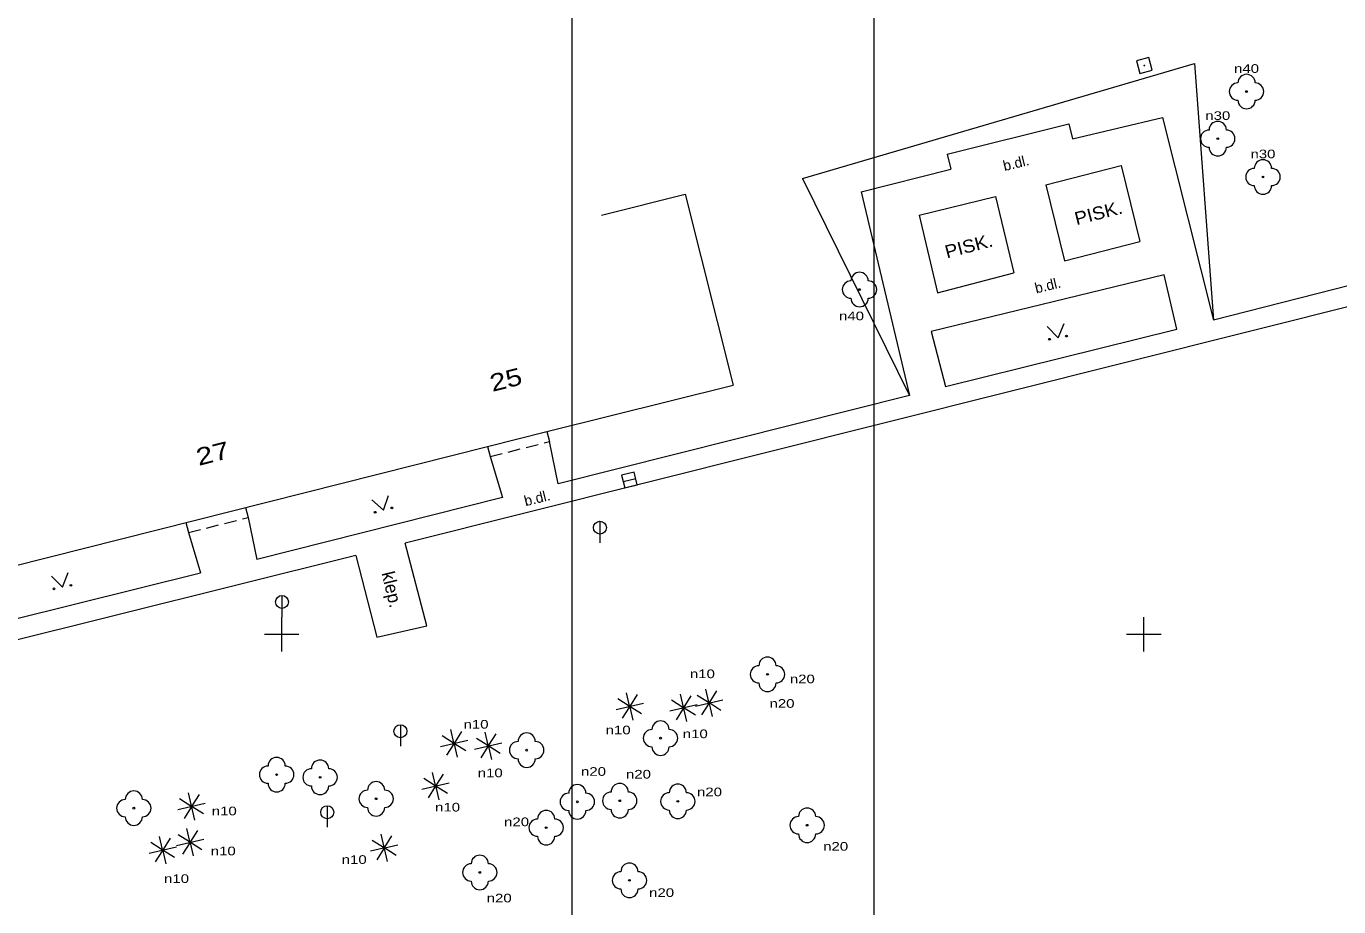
# Model space of a CAD drawing. Extents: x -670514 to -669423, y -1130798 to -1130123.
# Drawn here: x -669864.8 to -669788.7, y -1130615.8 to -1130564.8 of the extents above; entities that cross this region are included whole.
import ezdxf
from ezdxf.enums import TextEntityAlignment as Align

# ---------------------------------------------------------------- set-up
doc = ezdxf.new("R2010")
doc.units = 0
doc.header["$LTSCALE"] = 0.24
doc.linetypes.add('MEDIUM_DASHED', pattern=[4.5, 3, -1.5])
for name, color, linetype, lineweight in [('10', 7, 'Continuous', 13), ('14', 7, 'Continuous', 13), ('22', 7, 'Continuous', 13), ('26', 7, 'Continuous', 13), ('27', 7, 'Continuous', 13), ('36', 7, 'Continuous', 13), ('5', 7, 'Continuous', 13), ('60', 7, 'Continuous', 13), ('61', 7, 'Continuous', 13)]:
    doc.layers.add(name, color=color, linetype=linetype, lineweight=lineweight)
for name, color, linetype in [('40', 7, 'Continuous'), ('42', 7, 'Continuous'), ('44', 7, 'Continuous'), ('47', 7, 'Continuous')]:
    doc.layers.add(name, color=color, linetype=linetype)

msp = doc.modelspace()

# ---------------------------------------------------------------- linework, layer by layer
at = {"layer": '10'}
for p, q in [((-669811.412, -1130572.173), (-669804.351, -1130570.413)), ((-669804.351, -1130570.413), (-669804.142, -1130571.288)), ((-669811.412, -1130572.173), (-669811.191, -1130573.045)), ((-669816.404, -1130574.366), (-669811.191, -1130573.045)), ((-669813.027, -1130575.716), (-669808.608, -1130574.626)), ((-669808.608, -1130574.626), (-669807.545, -1130579.051)), ((-669813.027, -1130575.716), (-669811.961, -1130580.213)), ((-669778.633, -1130577.366), (-669795.958, -1130581.787)), ((-669811.961, -1130580.213), (-669807.545, -1130579.051)), ((-669786.393, -1130580.581), (-669842.834, -1130594.715)), ((-669851.942, -1130593.234), (-669851.442, -1130595.658)), ((-669855.411, -1130594.103), (-669854.71, -1130596.441)), ((-669845.694, -1130595.44), (-669878.012, -1130603.465)), ((-669845.694, -1130595.44), (-669844.483, -1130600.168))]:
    msp.add_line(p, q, dxfattribs=at)
for points in [[(-669804.142, -1130571.288), (-669798.922, -1130570.042), (-669795.958, -1130581.787)], [(-669805.696, -1130573.949), (-669801.327, -1130572.833), (-669800.231, -1130577.238)], [(-669816.404, -1130574.366), (-669813.599, -1130586.153), (-669833.962, -1130591.276), (-669834.473, -1130588.83)], [(-669805.696, -1130573.949), (-669804.6, -1130578.354), (-669800.231, -1130577.238)], [(-669837.918, -1130589.702), (-669837.194, -1130592.065), (-669851.442, -1130595.658)], [(-669844.483, -1130600.168), (-669841.58, -1130599.506), (-669842.834, -1130594.715)], [(-669869.812, -1130597.726), (-669869.347, -1130600.077), (-669854.71, -1130596.441)]]:
    msp.add_lwpolyline(points, dxfattribs=at)
msp.add_lwpolyline([(-669798.093, -1130582.322), (-669798.83, -1130579.158), (-669812.334, -1130582.46), (-669811.499, -1130585.643)], close=True, dxfattribs=at)
at = {"layer": '14'}
msp.add_line((-669819.795, -1130573.588), (-669813.599, -1130586.153), dxfattribs=at)
msp.add_lwpolyline([(-669819.795, -1130573.588), (-669797.073, -1130566.915), (-669795.958, -1130581.787)], dxfattribs=at)
at = {"layer": '22'}
for p, q in [((-669829.827, -1130604.139), (-669829.999, -1130603.385)), ((-669825.223, -1130603.937), (-669825.395, -1130603.183)), ((-669824.781, -1130603.287), (-669825.195, -1130603.943)), ((-669830.613, -1130604.359), (-669829.859, -1130604.187)), ((-669829.853, -1130604.159), (-669830.509, -1130603.745)), ((-669829.839, -1130604.213), (-669830.253, -1130604.869)), ((-669829.385, -1130603.489), (-669829.799, -1130604.145)), ((-669829.129, -1130604.613), (-669829.785, -1130604.199)), ((-669829.779, -1130604.171), (-669829.025, -1130603.999)), ((-669826.733, -1130604.239), (-669827.389, -1130603.825)), ((-669826.707, -1130604.219), (-669826.879, -1130603.465)), ((-669826.265, -1130603.569), (-669826.679, -1130604.225)), ((-669826.659, -1130604.251), (-669825.905, -1130604.079)), ((-669826.009, -1130604.157), (-669825.255, -1130603.985)), ((-669825.249, -1130603.957), (-669825.905, -1130603.543)), ((-669825.235, -1130604.011), (-669825.649, -1130604.667)), ((-669825.207, -1130604.017), (-669825.035, -1130604.771)), ((-669824.525, -1130604.411), (-669825.181, -1130603.997)), ((-669825.175, -1130603.969), (-669824.421, -1130603.797)), ((-669829.811, -1130604.219), (-669829.639, -1130604.973)), ((-669827.493, -1130604.439), (-669826.739, -1130604.267)), ((-669826.719, -1130604.293), (-669827.133, -1130604.949)), ((-669826.691, -1130604.299), (-669826.519, -1130605.053)), ((-669826.009, -1130604.693), (-669826.665, -1130604.279)), ((-669840.013, -1130606.282), (-669840.185, -1130605.528)), ((-669839.571, -1130605.632), (-669839.985, -1130606.288)), ((-669838.029, -1130606.429), (-669838.201, -1130605.675)), ((-669840.799, -1130606.502), (-669840.045, -1130606.33)), ((-669840.039, -1130606.302), (-669840.695, -1130605.888)), ((-669840.025, -1130606.356), (-669840.439, -1130607.012)), ((-669839.997, -1130606.362), (-669839.825, -1130607.116)), ((-669839.315, -1130606.756), (-669839.971, -1130606.342)), ((-669839.965, -1130606.314), (-669839.211, -1130606.142)), ((-669838.815, -1130606.649), (-669838.061, -1130606.477)), ((-669838.055, -1130606.449), (-669838.711, -1130606.035)), ((-669837.587, -1130605.779), (-669838.001, -1130606.435)), ((-669837.331, -1130606.903), (-669837.987, -1130606.489)), ((-669837.981, -1130606.461), (-669837.227, -1130606.289)), ((-669838.041, -1130606.503), (-669838.455, -1130607.159)), ((-669838.013, -1130606.509), (-669837.841, -1130607.263)), ((-669841.081, -1130608.758), (-669841.253, -1130608.004)), ((-669841.107, -1130608.778), (-669841.763, -1130608.364)), ((-669840.639, -1130608.108), (-669841.053, -1130608.764)), ((-669841.033, -1130608.79), (-669840.279, -1130608.618)), ((-669855.263, -1130609.958), (-669855.919, -1130609.544)), ((-669855.237, -1130609.938), (-669855.409, -1130609.184)), ((-669854.795, -1130609.288), (-669855.209, -1130609.944)), ((-669841.867, -1130608.978), (-669841.113, -1130608.806)), ((-669841.093, -1130608.832), (-669841.507, -1130609.488)), ((-669841.065, -1130608.838), (-669840.893, -1130609.592)), ((-669840.383, -1130609.232), (-669841.039, -1130608.818)), ((-669856.023, -1130610.158), (-669855.269, -1130609.986)), ((-669855.249, -1130610.012), (-669855.663, -1130610.668)), ((-669855.221, -1130610.018), (-669855.049, -1130610.772)), ((-669854.539, -1130610.412), (-669855.195, -1130609.998)), ((-669855.189, -1130609.97), (-669854.435, -1130609.798)), ((-669856.908, -1130612.467), (-669857.08, -1130611.713)), ((-669856.466, -1130611.817), (-669856.88, -1130612.473)), ((-669855.349, -1130612.033), (-669856.005, -1130611.619)), ((-669855.323, -1130612.013), (-669855.495, -1130611.259)), ((-669854.881, -1130611.363), (-669855.295, -1130612.019)), ((-669844.066, -1130612.338), (-669844.238, -1130611.584)), ((-669843.624, -1130611.688), (-669844.038, -1130612.344)), ((-669857.694, -1130612.687), (-669856.94, -1130612.515)), ((-669856.934, -1130612.487), (-669857.59, -1130612.073)), ((-669856.92, -1130612.541), (-669857.334, -1130613.197)), ((-669856.892, -1130612.547), (-669856.72, -1130613.301)), ((-669856.21, -1130612.941), (-669856.866, -1130612.527)), ((-669856.86, -1130612.499), (-669856.106, -1130612.327)), ((-669856.109, -1130612.233), (-669855.355, -1130612.061)), ((-669855.335, -1130612.087), (-669855.749, -1130612.743)), ((-669855.307, -1130612.093), (-669855.135, -1130612.847)), ((-669854.625, -1130612.487), (-669855.281, -1130612.073)), ((-669855.275, -1130612.045), (-669854.521, -1130611.873)), ((-669844.852, -1130612.558), (-669844.098, -1130612.386)), ((-669844.092, -1130612.358), (-669844.748, -1130611.944)), ((-669844.078, -1130612.412), (-669844.492, -1130613.068)), ((-669844.05, -1130612.418), (-669843.878, -1130613.172)), ((-669843.368, -1130612.812), (-669844.024, -1130612.398)), ((-669844.018, -1130612.37), (-669843.264, -1130612.198))]:
    msp.add_line(p, q, dxfattribs=at)
for centre, radius in [((-669794.047, -1130568.546), 0.05), ((-669795.717, -1130571.274), 0.05), ((-669793.096, -1130573.496), 0.05), ((-669816.489, -1130580.02), 0.05), ((-669821.829, -1130602.323), 0.05), ((-669829.819, -1130604.179), 0.04), ((-669825.215, -1130603.977), 0.04), ((-669826.699, -1130604.259), 0.04), ((-669840.005, -1130606.322), 0.04), ((-669838.021, -1130606.469), 0.04), ((-669828.03, -1130606.02), 0.05), ((-669835.792, -1130606.715), 0.05), ((-669850.293, -1130608.135), 0.05), ((-669847.773, -1130608.292), 0.05), ((-669841.073, -1130608.798), 0.04), ((-669844.524, -1130609.535), 0.05), ((-669858.575, -1130610.078), 0.05), ((-669855.229, -1130609.978), 0.04), ((-669832.857, -1130609.711), 0.05), ((-669830.396, -1130609.647), 0.05), ((-669827.028, -1130609.685), 0.05), ((-669819.529, -1130611.069), 0.05), ((-669834.662, -1130611.207), 0.05), ((-669856.9, -1130612.507), 0.04), ((-669855.315, -1130612.053), 0.04), ((-669844.058, -1130612.378), 0.04), ((-669838.512, -1130613.803), 0.05), ((-669829.832, -1130614.263), 0.05)]:
    msp.add_circle(centre, radius, dxfattribs=at)
for centre, start, end in [((-669794.047, -1130568.046), 0, 180), ((-669794.547, -1130568.546), 90, 270), ((-669793.547, -1130568.546), 270, 90), ((-669794.047, -1130569.046), 180, 0), ((-669795.717, -1130570.774), 0, 180), ((-669796.217, -1130571.274), 90, 270), ((-669795.217, -1130571.274), 270, 90), ((-669795.717, -1130571.774), 180, 0), ((-669793.596, -1130573.496), 90, 270), ((-669793.096, -1130572.996), 0, 180), ((-669792.596, -1130573.496), 270, 90), ((-669793.096, -1130573.996), 180, 0), ((-669816.489, -1130579.52), 0, 180), ((-669816.989, -1130580.02), 90, 270), ((-669815.989, -1130580.02), 270, 90), ((-669816.489, -1130580.52), 180, 0), ((-669822.329, -1130602.323), 90, 270), ((-669821.829, -1130601.823), 0, 180), ((-669821.329, -1130602.323), 270, 90), ((-669821.829, -1130602.823), 180, 0), ((-669835.792, -1130606.215), 0, 180), ((-669828.53, -1130606.02), 90, 270), ((-669828.03, -1130605.52), 0, 180), ((-669827.53, -1130606.02), 270, 90), ((-669836.292, -1130606.715), 90, 270), ((-669835.292, -1130606.715), 270, 90), ((-669850.293, -1130607.635), 0, 180), ((-669835.792, -1130607.215), 180, 0), ((-669828.03, -1130606.52), 180, 0), ((-669850.793, -1130608.135), 90, 270), ((-669849.793, -1130608.135), 270, 90), ((-669848.273, -1130608.292), 90, 270), ((-669847.773, -1130607.792), 0, 180), ((-669847.273, -1130608.292), 270, 90), ((-669850.293, -1130608.635), 180, 0), ((-669844.524, -1130609.035), 0, 180), ((-669832.857, -1130609.211), 0, 180), ((-669830.396, -1130609.147), 0, 180), ((-669827.028, -1130609.185), 0, 180), ((-669858.575, -1130609.578), 0, 180), ((-669847.773, -1130608.792), 180, 0), ((-669845.024, -1130609.535), 90, 270), ((-669844.024, -1130609.535), 270, 90), ((-669833.357, -1130609.711), 90, 270), ((-669832.357, -1130609.711), 270, 90), ((-669830.896, -1130609.647), 90, 270), ((-669829.896, -1130609.647), 270, 90), ((-669827.528, -1130609.685), 90, 270), ((-669826.528, -1130609.685), 270, 90), ((-669859.075, -1130610.078), 90, 270), ((-669858.075, -1130610.078), 270, 90), ((-669844.524, -1130610.035), 180, 0), ((-669834.662, -1130610.707), 0, 180), ((-669832.857, -1130610.211), 180, 0), ((-669830.396, -1130610.147), 180, 0), ((-669827.028, -1130610.185), 180, 0), ((-669819.529, -1130610.569), 0, 180), ((-669858.575, -1130610.578), 180, 0), ((-669835.162, -1130611.207), 90, 270), ((-669834.162, -1130611.207), 270, 90), ((-669820.029, -1130611.069), 90, 270), ((-669819.029, -1130611.069), 270, 90), ((-669834.662, -1130611.707), 180, 0), ((-669819.529, -1130611.569), 180, 0), ((-669839.012, -1130613.803), 90, 270), ((-669838.512, -1130613.303), 0, 180), ((-669838.012, -1130613.803), 270, 90), ((-669829.832, -1130613.763), 0, 180), ((-669830.332, -1130614.263), 90, 270), ((-669829.332, -1130614.263), 270, 90), ((-669838.512, -1130614.303), 180, 0), ((-669829.832, -1130614.763), 180, 0)]:
    msp.add_arc(centre, 0.5, start, end, dxfattribs=at)
at = {"layer": '26'}
msp.add_lwpolyline([(-669800.241, -1130567.49), (-669799.516, -1130567.299), (-669799.707, -1130566.574), (-669800.432, -1130566.765)], close=True, dxfattribs=at)
msp.add_circle((-669799.9739, -1130567.032), 0.02, dxfattribs=at)
at = {"layer": '27'}
for p, q in [((-669830.195, -1130591.152), (-669829.467, -1130590.972)), ((-669831.546, -1130593.445), (-669831.546, -1130594.695)), ((-669849.984, -1130597.75), (-669849.984, -1130599)), ((-669843.115, -1130605.244), (-669843.115, -1130606.494)), ((-669847.36, -1130609.939), (-669847.36, -1130611.189))]:
    msp.add_line(p, q, dxfattribs=at)
msp.add_lwpolyline([(-669830.105, -1130591.515), (-669829.377, -1130591.335), (-669829.557, -1130590.607), (-669830.285, -1130590.787)], close=True, dxfattribs=at)
for centre in [(-669831.5456, -1130593.8201), (-669849.9836, -1130598.1251), (-669843.1146, -1130605.6191), (-669847.3596, -1130610.3141)]:
    msp.add_circle(centre, 0.375, dxfattribs=at)
at = {"layer": '36'}
for points in [[(-669805.611, -1130582.164), (-669804.981, -1130582.81), (-669804.628, -1130581.98)], [(-669844.768, -1130592.2), (-669844.095, -1130592.8), (-669843.8, -1130591.948)], [(-669863.358, -1130596.632), (-669862.714, -1130597.263), (-669862.379, -1130596.426)]]:
    msp.add_lwpolyline(points, dxfattribs=at)
for centre in [(-669805.4728, -1130582.9015), (-669804.4898, -1130582.7177), (-669843.6111, -1130592.6734), (-669844.5788, -1130592.9257), (-669863.2035, -1130597.3657), (-669862.2249, -1130597.1599)]:
    msp.add_circle(centre, 0.05, dxfattribs=at)
at = {"layer": '5'}
for p, q in [((-669831.456, -1130575.714), (-669826.607, -1130574.495)), ((-669826.607, -1130574.495), (-669823.827, -1130585.555)), ((-669834.62, -1130588.248), (-669834.473, -1130588.83)), ((-669838.065, -1130589.12), (-669837.918, -1130589.702)), ((-669852.09, -1130592.649), (-669851.943, -1130593.231)), ((-669855.558, -1130593.521), (-669855.411, -1130594.103))]:
    msp.add_line(p, q, dxfattribs=at)
at = {"layer": '5', "linetype": 'MEDIUM_DASHED'}
for p, q in [((-669837.918, -1130589.702), (-669834.473, -1130588.83)), ((-669855.411, -1130594.103), (-669851.942, -1130593.234))]:
    msp.add_line(p, q, dxfattribs=at)
at = {"layer": '5'}
for points in [[(-669838.065, -1130589.12), (-669834.62, -1130588.248), (-669823.827, -1130585.555)], [(-669873.428, -1130598.013), (-669869.959, -1130597.144), (-669838.065, -1130589.12)]]:
    msp.add_lwpolyline(points, dxfattribs=at)
at = {"layer": '60'}
for points in [[(-669833.172, -1130763.536), (-669423.172, -1130763.536), (-669423.172, -1130476.536), (-669833.172, -1130476.536)], [(-670225.642, -1130798.198), (-669815.642, -1130798.198), (-669815.642, -1130511.198), (-670225.642, -1130511.198)]]:
    msp.add_lwpolyline(points, close=True, dxfattribs=at)
at = {"layer": '61'}
for p, q in [((-669850, -1130601), (-669850, -1130599)), ((-669800, -1130601), (-669800, -1130599)), ((-669851, -1130600), (-669849, -1130600)), ((-669801, -1130600), (-669799, -1130600))]:
    msp.add_line(p, q, dxfattribs=at)

# ---------------------------------------------------------------- texts
at = {"layer": '22', "width": 1.3}
for s, p in [('n40', (-669794.0465, -1130567.46)), ('n30', (-669795.7165, -1130570.188)), ('n30', (-669793.0955, -1130572.41)), ('n40', (-669816.9555, -1130581.799))]:
    msp.add_text(s, height=0.499, dxfattribs=at).set_placement(p, align=Align.CENTER)
at = {"layer": '40'}
for rotation, p in [(13.856, (-669807.3468, -1130572.9769)), (13.74, (-669805.5053, -1130580.0699)), (14.059, (-669835.1174, -1130592.3985))]:
    msp.add_text('b.dl.', height=0.6, rotation=rotation, dxfattribs=at).set_placement(p, align=Align.CENTER)
at = {"layer": '42', "width": 1.1}
for rotation, p in [(14.329, (-669802.5423, -1130575.944)), (14.742, (-669810.0629, -1130577.8616))]:
    msp.add_text('PISK.', height=0.75, rotation=rotation, dxfattribs=at).set_placement(p, align=Align.CENTER)
at = {"layer": '42'}
msp.add_text('klep.', height=0.75, rotation=283.484, dxfattribs=at).set_placement((-669843.9671, -1130597.4876), align=Align.CENTER)
at = {"layer": '44'}
for s, rotation, width, p in [('25', 14.204, 1.25, (-669836.8777, -1130585.725)), ('27', 14.122, 1.3, (-669853.878, -1130590.0048))]:
    msp.add_text(s, height=1, rotation=rotation, dxfattribs=dict(at, width=width)).set_placement(p, align=Align.CENTER)
at = {"layer": '47', "width": 1.3}
for s, p in [('n10', (-669825.6035, -1130602.541)), ('n20', (-669819.8085, -1130602.84)), ('n20', (-669820.9865, -1130604.259)), ('n10', (-669838.7305, -1130605.467)), ('n10', (-669830.4895, -1130605.799)), ('n10', (-669826.0155, -1130606.02)), ('n10', (-669837.9065, -1130608.283)), ('n20', (-669831.9195, -1130608.203)), ('n20', (-669829.3125, -1130608.361)), ('n20', (-669825.1915, -1130609.387)), ('n10', (-669853.3295, -1130610.492)), ('n10', (-669840.3795, -1130610.271)), ('n20', (-669836.3775, -1130611.122)), ('n10', (-669853.3885, -1130612.81)), ('n20', (-669817.8745, -1130612.542)), ('n10', (-669845.7945, -1130613.307)), ('n10', (-669856.0965, -1130614.411)), ('n20', (-669827.9675, -1130615.224)), ('n20', (-669837.3865, -1130615.539))]:
    msp.add_text(s, height=0.5, dxfattribs=at).set_placement(p, align=Align.CENTER)

doc.saveas('drawing.dxf')
